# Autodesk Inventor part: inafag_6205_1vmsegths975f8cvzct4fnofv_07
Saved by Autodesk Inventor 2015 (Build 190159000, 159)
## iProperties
Company: TraceParts S.A.
Created: 2012-12
Part Number: inafag_6205_1vmsegths975f8cvzct4fnofv_07
Checked By: TraceParts S.A.
Catalog Web Link: www.traceparts.com
Document SubType Name: Modeling
Designer: TraceParts
Material: Generic
Density: 1 g/cm^3
Appearance: Default
Author: TraceParts
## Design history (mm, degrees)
feature "inafag_6205_1vmsegths975f8cvzct4fnofv"
body "Solid1"
